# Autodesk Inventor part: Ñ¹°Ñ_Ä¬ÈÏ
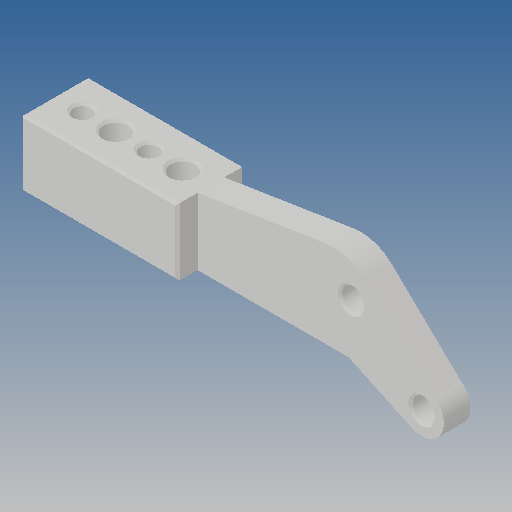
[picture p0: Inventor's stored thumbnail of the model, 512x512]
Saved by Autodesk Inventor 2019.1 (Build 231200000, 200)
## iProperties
Created: 2012-10
Part Number: Ñ¹°Ñ_Ä¬ÈÏ
Material: Ogólny
Document SubType Name: Modeling
Designer: CADENGINEERING4
Density: 1 g/cm^3
Appearance: Domyślna
Author: CADENGINEERING4
Revision Number: ÈÎºÎ
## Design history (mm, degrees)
feature "NONE"
node "Bryła1"
